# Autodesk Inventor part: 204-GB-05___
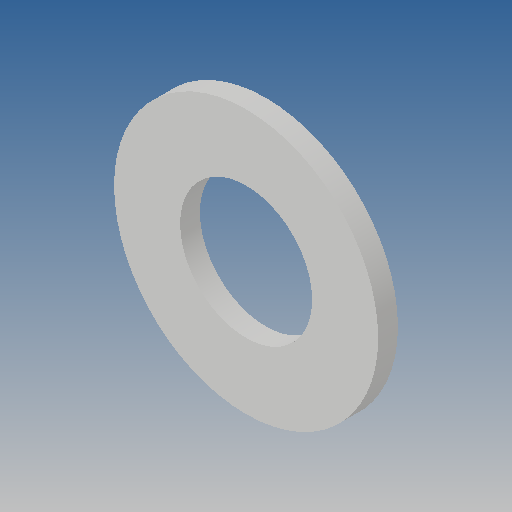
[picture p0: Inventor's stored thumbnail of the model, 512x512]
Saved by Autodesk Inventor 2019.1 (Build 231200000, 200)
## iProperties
Created: 2010-06
Part Number: 204-GB-05___
Material: Ogólny
Document SubType Name: Modeling
Designer: CADENGINEERING4
Density: 1 g/cm^3
Appearance: Domyślna
Author: CADENGINEERING4
Revision Number: ANY
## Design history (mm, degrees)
feature "NONE"
node "Bryła1"
